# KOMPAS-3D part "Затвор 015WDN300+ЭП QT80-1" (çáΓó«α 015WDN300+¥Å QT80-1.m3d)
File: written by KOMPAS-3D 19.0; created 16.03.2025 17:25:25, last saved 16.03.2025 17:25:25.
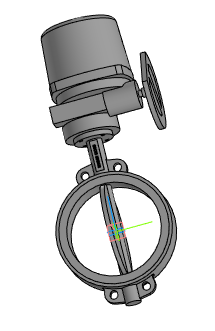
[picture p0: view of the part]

Document properties: Полное имя файла: Затвор 015WDN300+ЭП QT80-1.a3d

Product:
- Part/product: Затвор 015WDN300+ЭП QT80-1
    Масса: 159.801

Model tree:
1. Операция без истории:1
